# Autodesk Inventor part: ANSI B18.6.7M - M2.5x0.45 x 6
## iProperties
Comments: To add or edit properties for Autodesk Inventor files, use iProperties.
Created: 2004-07
Part Number: ANSI B18.6.7M - M2.5x0.45 x 6
Vendor: Autodesk Inc.
Document SubType Name: Modeling
Designer: John Blackburn
Material: Default
Description: Slotted Pan Head Machine Screw (Regular Thread - Metric)
Standard: ANSI B18.6.7M
Alert: To add or edit properties for Autodesk Inventor files, use iProperties.
Control State: 0
Master: False
Checked Out: False
Shininess: 64.0
Length Units: 11269
Angle Units: 11279
Time Units: 11290
Mass Units: 11283
Length Display Precision: 3
Angle Display Precision: 2
Compacted: True
EGR: 1
Classification: un/spsc 31161501
Density: 0.0
Volumn: 0.0
Area: 0.0
PropertySet Name: Model Information
Author: John Blackburn
Revision Number: 8
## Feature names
1. Body [Revolution]
2. Fillet1
3. Slot [Extrusion]
4. Chamfer1
